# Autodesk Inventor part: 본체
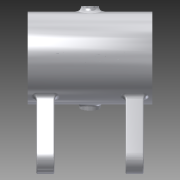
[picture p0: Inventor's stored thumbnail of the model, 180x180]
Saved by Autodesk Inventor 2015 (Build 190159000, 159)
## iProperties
Created: 2016-04
Part Number: 본체
Material: 알루미늄 6061
Document SubType Name: Modeling
Designer: Administrator
Density: 2.7 g/cm^3
Appearance: 알루미늄 - 평지
Mass: 210.316 g
Surface Area: 327.047 cm^2
Volume: 77.8948 cm^3
Author: Administrator
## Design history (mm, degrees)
sketch "스케치1"
  geometry: C1 r 26 at (0, 0); 1 further point
  constraints: 1 centre point, 1 coincident
  dimensions: "d0" = 52 diameter of C1
extrude "돌출1" new body sketch "스케치1" distance "d1" = 70; taper "d2" = 0 deg
node "작업 평면1"
node "작업 평면2"
node "작업 평면3"
sketch "스케치4"
  geometry: C1 r 5 at (0, 35); 1 further point
  constraints: 1 centre point
  dimensions: "d28" = 10 diameter of C1
extrude "돌출2" join sketch "스케치4" distance "d29" = 3; taper "d30" = 0 deg; dims "d31" = 1.5, "d32" = 0
node "작업 평면8"
sketch "스케치7"
  geometry: C1 r 6 at (0, -35); 1 further point
  constraints: 1 centre point
  dimensions: "d39" = 12 diameter of C1
extrude "돌출3" join sketch "스케치7" stored distance "d40" = 3; taper "d41" = 0 deg
sketch "스케치8"
  geometry: C1 r 26 at (0, 0) reference; C2 r 16 at (0, 0)
  constraints: 1 centre point, 1 coincident
  dimensions: "d42" = 32 diameter of C2
extrude "돌출4" cut sketch "스케치8" distance "d43" = 12; taper "d44" = 0 deg
sketch "스케치9"
  geometry: C1 r 26 at (0, 0) reference; C2 r 16 at (0, 0)
  constraints: 1 centre point, 1 coincident
  dimensions: "d45" = 32 diameter of C2
extrude "돌출5" cut sketch "스케치9" distance "d46" = 12; taper "d47" = 0 deg
sketch "스케치10"
  geometry: C1 r 16 at (0, 0) reference; C2 r 14 at (0, 0)
  constraints: 1 centre point, 1 coincident
  dimensions: "d48" = 28 diameter of C2
extrude "돌출6" cut sketch "스케치10" distance "d49" = 2; taper "d50" = 0 deg
sketch "스케치11"
  geometry: C1 r 16 at (0, 0) reference; C2 r 14 at (0, 0)
  constraints: 1 centre point, 1 coincident
  dimensions: "d51" = 28 diameter of C2
extrude "돌출7" cut sketch "스케치11" distance "d52" = 2; taper "d53" = 0 deg
sketch "스케치12"
  geometry: C1 r 14 at (0, 0) reference; C2 r 21 at (0, 0)
  constraints: 1 centre point, 1 coincident
  dimensions: "d54" = 42 diameter of C2
extrude "돌출8" cut sketch "스케치12" distance "d55" = 42; taper "d56" = 0 deg
sketch "스케치13"
  geometry: 3 further points
  constraints: 1 coincident
hole "구멍1" sketch "스케치13" at (0, -35) diameter "d59" = 5.188; stored, may be unused: countersink angle "d63" = 90 deg, drill point angle "d65" = 118 deg; dims "d60" = 12, "d61" = 4, "d62" = 2, "d64" = 16
sketch "스케치15"
  geometry: C1 r 6 at (0, 0) reference; 1 further point
hole "구멍2" sketch "스케치15" at (0, 0) diameter "d67" = 5.188; stored, may be unused: countersink angle "d71" = 90 deg, drill point angle "d73" = 118 deg; dims "d68" = 12, "d69" = 4, "d70" = 2, "d72" = 16
chamfer "모따기1" distance "d85" = 1; stored, may be unused: second distance "d86" = 2, angle "d87" = 45 deg
sketch "스케치17"
  geometry: 4 further points
hole "구멍3" sketch "스케치17" at (20.999, 0.18), (0.18, -20.999), (-20.999, -0.18), (-0.18, 20.999) diameter "d92" = 3.242; stored, may be unused: countersink angle "d96" = 90 deg, drill point angle "d98" = 118 deg; dims "d93" = 8, "d94" = 4, "d95" = 2, "d97" = 10
sketch "스케치18"
  geometry: C1 r 1.621 at (0.18, 20.999) reference; C2 r 1.621 at (20.999, -0.18) reference; C3 r 1.621 at (-0.18, -20.999) reference; C4 r 1.621 at (-20.999, 0.18) reference
hole "구멍4" sketch "스케치18" at (-20.999, 0.18), (20.999, -0.18), (-0.18, -20.999), (0.18, 20.999) diameter "d99" = 3.242; stored, may be unused: countersink angle "d103" = 90 deg, drill point angle "d105" = 118 deg; dims "d100" = 8, "d101" = 4, "d102" = 2, "d104" = 10
node "작업 평면9"
sketch "스케치19"
  geometry: L1 (0, 0)-(31.466, -54.5); L2 (0, 0)-(-31.466, -54.5); L3 (-27.135, -62)-(27.135, -62); C1 r 16 at (0, 0) reference; A1 r 5 centre (-27.135, -57) between (-31.466, -54.5) and (-27.135, -62); A2 r 5 centre (27.135, -57) between (27.135, -62) and (31.466, -54.5); 1 further point
  constraints: 6 end point, 4 point on circle, 4 tangent, 2 centre point, 1 equal radius, 1 horizontal
  dimensions: "d112" = 5 radius of A1
feature "리브3" sketch "스케치19" dims "d113" = 3, "d114" = 10, "d115" = 0, "d116" = 0, "d117" = 1, "d118" = 1
node "작업 평면10"
sketch "스케치20"
  geometry: L1 (27.135, -62)-(-27.135, -62) reference; L2 (0, 0)-(31.466, -54.5); L3 (8, -13.856)-(0, 0) reference; L4 (27.135, -62)-(-27.135, -62); L5 (-31.466, -54.5)-(0, 0); A1 r 5 centre (-27.135, -57) between (-31.466, -54.5) and (-27.135, -62); A2 r 5 centre (27.135, -57) between (27.135, -62) and (31.466, -54.5)
  constraints: 6 end point, 4 point on circle, 4 tangent, 2 centre point, 1 collinear, 1 equal radius
  dimensions: "d120" = 5 radius of A1
feature "리브4" sketch "스케치20" dims "d121" = 3, "d122" = 10, "d123" = 0, "d124" = 0, "d125" = 1, "d126" = 1
sketch "스케치21"
  geometry: C1 r 26 at (0, 0) reference; C2 r 16 at (0, 0)
  constraints: 1 centre point, 1 coincident
  dimensions: "d127" = 32 diameter of C2
extrude "돌출10" cut sketch "스케치21" distance "d128" = 12; taper "d129" = 0 deg
sketch "스케치22"
  geometry: L1 (0, 6)-(9.435, -10.343) reference; L2 (-9.435, -10.343)-(0, 6) reference; L3 (0, 0)-(-7, -12.124) reference; L4 (7, -12.124)-(0, 0) reference; A1 r 14 centre (0, 0) between (9.435, -10.343) and (-9.435, -10.343) reference; A2 r 14 centre (0, 0) between (-7, -12.124) and (7, -12.124) reference; 1 further point
  constraints: 1 coincident, 3 other
extrude "돌출11" cut sketch "스케치22" stored distance "d130" = 0; taper "d131" = 0 deg
sketch "스케치23"
  geometry: C1 r 14 at (0, 0) reference; C2 r 16 at (0, 0)
  constraints: 1 centre point, 1 coincident
  dimensions: "d132" = 32 diameter of C2
extrude "돌출12" cut sketch "스케치23" distance "d133" = 12; taper "d134" = 0 deg
sketch "스케치24"
  geometry: L1 (-12.99, -16.5)-(-9.435, -10.343) reference; L2 (9.435, -10.343)-(12.99, -16.5) reference; C1 r 21 at (0, 0); A1 r 14 centre (0, 0) between (9.435, -10.343) and (-9.435, -10.343) reference; A2 r 21 centre (0, 0) between (12.99, -16.5) and (-12.99, -16.5) reference
  constraints: 1 centre point, 1 coincident
  dimensions: "d135" = 42 diameter of C1
extrude "돌출13" cut sketch "스케치24" distance "d136" = 42; taper "d137" = 0 deg
fillet "모깎기3" dims "d138" = 0.5, "d139" = 3, "d140" = 2, "d155" = 0.3
sketch "스케치25"
  geometry: L1 (54.271, 9.5)-(0, 9.5) reference; L2 (0, -0.5)-(54.271, -0.5) reference; L3 (0, 9.5)-(54.271, 9.5) reference; L4 (25.695, 14.5)-(28.937, 14.5) reference; L5 (27.135, -55.5)-(97.135, -55.5); C1 r 3 at (7.135, 4.5); C2 r 3 at (47.135, 4.5); C3 r 3 at (7.135, -45.5); C4 r 3 at (47.135, -45.5)
  constraints: 4 centre point, 2 end point, 1 horizontal
  dimensions: "d144" = 6 diameter of C1; "d145" = 6 diameter of C2
extrude "돌출14" cut sketch "스케치25" distance "d148" = 10; taper "d149" = 0 deg
node "작업 평면11"
sketch "스케치26"
  geometry: L1 (26, 70)-(-26, 70) reference; L2 (26, 0)-(26, 70) reference; 2 further points
  constraints: 1 other
feature "엠보싱1" sketch "스케치26" dims "d153" = 0.5, "d154" = 0
node "솔리드1"
other parameters: "d3" = -15, "d15" = -15, "d26" = 26, "d106" = 5, "d119" = -5, "d150" = 26
